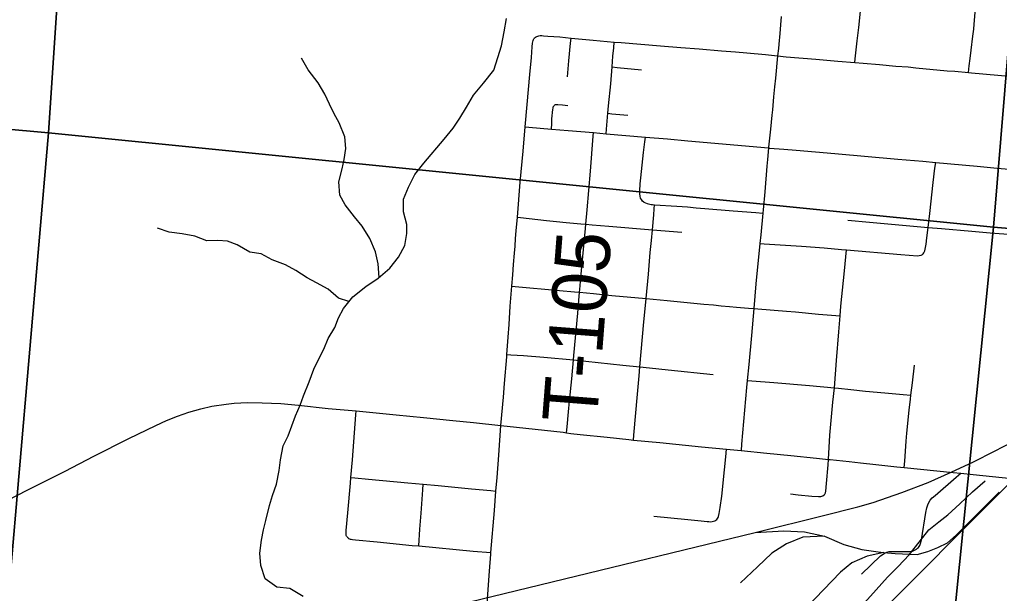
# Model space of a CAD drawing. Extents: x 0 to 1067, y 0 to 440.
# Drawn here: x 800.649 to 801.667, y 352.129 to 352.726 of the extents above; entities that cross this region are included whole.
import ezdxf

# ---------------------------------------------------------------- set-up
doc = ezdxf.new("R2010")
doc.units = 0
for name, color, linetype in [('GM_X_City_Street', 7, 'Continuous'), ('GM_X_County_Road', 7, 'Continuous'), ('GM_X_Minor_River', 7, 'Continuous'), ('GM_X_Rail_Line', 7, 'Continuous'), ('GM_X_Section', 7, 'Continuous'), ('GM_X_State_Route', 7, 'Continuous'), ('GM_X_Township_Road', 7, 'Continuous'), ('GM_X_Township_Road_Text', 7, 'Continuous'), ('GM_X_US_Route', 7, 'Continuous')]:
    doc.layers.add(name, color=color, linetype=linetype)

msp = doc.modelspace()

# ---------------------------------------------------------------- linework, layer by layer
at = {"layer": 'GM_X_City_Street'}
for p, q in [((801.2456, 352.6084), (801.2588, 352.6073)), ((801.2588, 352.6073), (801.2997, 352.6038))]:
    msp.add_line(p, q, dxfattribs=at)
for points in [[(801.5172, 352.6814), (801.5176, 352.685), (801.5184, 352.6915), (801.5198, 352.7039), (801.5214, 352.7179), (801.5236, 352.7383), (801.5243, 352.7457), (801.5246, 352.7506), (801.5256, 352.7626), (801.5278, 352.7882), (801.5297, 352.8098), (801.5302, 352.8166), (801.5309, 352.8233), (801.532, 352.8332), (801.5329, 352.8412), (801.5341, 352.8529), (801.5353, 352.8661), (801.5368, 352.883), (801.5376, 352.8918), (801.5379, 352.8957)], [(801.6353, 352.6709), (801.636, 352.6779), (801.6369, 352.6856), (801.638, 352.694), (801.6398, 352.7086), (801.6407, 352.7159), (801.6412, 352.7213), (801.6424, 352.7335), (801.6426, 352.7371), (801.6434, 352.7479), (801.6438, 352.7522)], [(801.186, 352.7081), (801.1869, 352.7085), (801.1879, 352.7089), (801.189, 352.7091), (801.1902, 352.7093), (801.191, 352.7093), (801.1918, 352.7093), (801.1936, 352.7092), (801.1981, 352.7089), (801.2107, 352.7079), (801.2223, 352.7066), (801.2453, 352.7045), (801.2672, 352.7026), (801.2744, 352.702), (801.3153, 352.6987), (801.3364, 352.697), (801.3556, 352.6955), (801.3785, 352.6935), (801.3933, 352.6925), (801.4051, 352.6915), (801.4243, 352.6896), (801.437, 352.6883), (801.4459, 352.6874), (801.4768, 352.6848), (801.4997, 352.6829), (801.5172, 352.6814), (801.5257, 352.6806), (801.543, 352.6792), (801.5597, 352.6777), (801.5727, 352.6767), (801.5807, 352.6759), (801.6131, 352.6728), (801.6211, 352.6722), (801.6353, 352.6709), (801.6385, 352.6706), (801.7086, 352.6645)], [(801.2186, 352.6663), (801.2201, 352.6832), (801.2218, 352.7016), (801.2223, 352.7066)], [(801.2588, 352.6073), (801.2592, 352.6119), (801.2602, 352.6246), (801.2605, 352.6285), (801.2611, 352.6363), (801.2636, 352.6591), (801.2651, 352.6767), (801.2659, 352.6881), (801.2667, 352.6965), (801.2672, 352.7026)], [(801.2651, 352.6767), (801.2702, 352.6762), (801.2956, 352.6737)], [(801.202, 352.6121), (801.2023, 352.6178), (801.2025, 352.6228), (801.2034, 352.6326), (801.2036, 352.634), (801.2039, 352.6352), (801.2043, 352.6361), (801.2049, 352.6367), (801.2056, 352.6372), (801.2063, 352.6375), (801.2071, 352.6376), (801.2086, 352.6376), (801.2136, 352.6372), (801.2188, 352.6368)], [(801.2605, 352.6285), (801.2648, 352.6281), (801.2814, 352.6267)], [(801.1747, 352.6144), (801.1785, 352.6141), (801.202, 352.6121)], [(801.202, 352.6121), (801.2193, 352.6107), (801.2456, 352.6084)], [(801.2176, 352.2963), (801.2182, 352.3023), (801.2198, 352.3179), (801.2208, 352.329), (801.2232, 352.3525), (801.2249, 352.3723), (801.2253, 352.3766), (801.2292, 352.4207), (801.2312, 352.4425), (801.2314, 352.4452), (801.2325, 352.4576), (801.2372, 352.5088), (801.2376, 352.5131), (801.2391, 352.528), (801.2425, 352.5684), (801.2453, 352.6046), (801.2456, 352.6084)], [(801.298, 352.5362), (801.2966, 352.5373), (801.2954, 352.5388), (801.2946, 352.5404), (801.2941, 352.5425), (801.2939, 352.5447), (801.2939, 352.5496), (801.294, 352.5533), (801.2942, 352.5552), (801.295, 352.5615), (801.2976, 352.5879), (801.2991, 352.599), (801.2997, 352.6038)], [(801.2997, 352.6038), (801.3227, 352.6018), (801.3437, 352.5998), (801.4275, 352.5925)], [(801.4275, 352.5925), (801.4284, 352.5924), (801.4433, 352.5911), (801.4563, 352.5901), (801.4965, 352.5867), (801.562, 352.5807), (801.588, 352.5786), (801.6012, 352.5774)], [(801.5861, 352.4809), (801.5874, 352.4817), (801.5882, 352.4825), (801.589, 352.4835), (801.5898, 352.4854), (801.5907, 352.4889), (801.5912, 352.4924), (801.592, 352.4989), (801.5933, 352.5098), (801.5951, 352.5244), (801.5986, 352.5566), (801.6005, 352.5714), (801.6012, 352.5774)], [(801.6012, 352.5774), (801.6442, 352.5736), (801.6652, 352.5716), (801.698, 352.5688)], [(801.298, 352.5362), (801.2996, 352.5354), (801.3013, 352.5348), (801.3027, 352.5344), (801.3042, 352.534), (801.3056, 352.5337), (801.3071, 352.5336), (801.309, 352.5334), (801.3321, 352.5319), (801.3433, 352.5311), (801.3525, 352.5302), (801.3612, 352.5296), (801.3908, 352.5271), (801.4142, 352.5252), (801.4216, 352.5246)], [(801.2871, 352.2887), (801.2876, 352.2939), (801.2914, 352.3366), (801.2931, 352.3556), (801.2939, 352.3647), (801.2981, 352.4116), (801.3001, 352.432), (801.3004, 352.4358), (801.3027, 352.4611), (801.3047, 352.4839), (801.3058, 352.4962), (801.3068, 352.5072), (801.3082, 352.5228), (801.3086, 352.5292), (801.309, 352.5334)], [(801.1665, 352.5206), (801.1698, 352.5202), (801.1968, 352.5171), (801.2071, 352.516), (801.2173, 352.515), (801.2325, 352.5136), (801.2376, 352.5131), (801.2442, 352.5127), (801.2615, 352.5113), (801.3068, 352.5072), (801.3375, 352.505)], [(801.5101, 352.5173), (801.5324, 352.5153), (801.5933, 352.5098), (801.6074, 352.5086), (801.6387, 352.5058), (801.658, 352.5042), (801.6864, 352.5022), (801.7286, 352.4997), (801.7295, 352.4996), (801.7413, 352.4985), (801.753, 352.4974), (801.7634, 352.4961), (801.7689, 352.4953)], [(801.4186, 352.4932), (801.423, 352.4929), (801.4619, 352.4903), (801.4854, 352.4885), (801.5033, 352.487), (801.5086, 352.4864), (801.565, 352.4817), (801.5824, 352.4804), (801.5842, 352.4805), (801.5861, 352.4809)], [(801.4898, 352.2686), (801.4913, 352.2939), (801.4943, 352.328), (801.496, 352.343), (801.498, 352.3713), (801.5005, 352.4011), (801.5019, 352.4179), (801.5028, 352.4281), (801.5055, 352.4546), (801.5066, 352.4648), (801.5086, 352.4864)], [(801.1609, 352.4487), (801.1641, 352.4484), (801.2103, 352.4442), (801.2258, 352.443), (801.2312, 352.4425), (801.2456, 352.4411), (801.2647, 352.4392), (801.3004, 352.4358), (801.3222, 352.434), (801.3604, 352.4302), (801.3703, 352.4292), (801.3783, 352.4284), (801.3869, 352.4276), (801.3943, 352.4269), (801.4066, 352.4259), (801.4121, 352.4254), (801.4333, 352.4238), (801.4463, 352.4228), (801.4555, 352.422), (801.4794, 352.4198), (801.4976, 352.4183), (801.5019, 352.4179)], [(801.1557, 352.3778), (801.1599, 352.3775), (801.1729, 352.3767), (801.1942, 352.375), (801.2249, 352.3723), (801.2761, 352.3665), (801.2939, 352.3647), (801.3039, 352.3637), (801.3231, 352.3617), (801.3699, 352.3569)], [(801.5685, 352.26), (801.569, 352.2666), (801.5707, 352.2875), (801.5714, 352.2959), (801.5736, 352.3199), (801.5749, 352.3311), (801.5754, 352.3353), (801.5771, 352.3483), (801.5791, 352.3666)], [(801.4054, 352.3506), (801.4101, 352.3503), (801.4331, 352.3487), (801.4701, 352.3455), (801.496, 352.343), (801.5002, 352.3426), (801.5132, 352.3414), (801.5282, 352.3397), (801.5484, 352.3379), (801.5675, 352.336), (801.5754, 352.3353)], [(801.3729, 352.2055), (801.3737, 352.2062), (801.3746, 352.2073), (801.3751, 352.2082), (801.3755, 352.2093), (801.3762, 352.2123), (801.3773, 352.2185), (801.3789, 352.2302), (801.3817, 352.2579), (801.383, 352.2714), (801.3838, 352.2794)], [(801.4504, 352.2329), (801.4584, 352.2319), (801.4726, 352.2305), (801.4794, 352.2299), (801.4806, 352.2299), (801.4819, 352.2301), (801.483, 352.2303), (801.484, 352.2308), (801.4852, 352.2317), (801.486, 352.2326), (801.4866, 352.2337), (801.487, 352.2354), (801.4879, 352.2435), (801.4894, 352.2631), (801.4898, 352.2686)], [(801.5866, 352.1848), (801.591, 352.2133), (801.592, 352.2181), (801.5929, 352.2212), (801.5941, 352.2239), (801.5956, 352.2263), (801.5976, 352.2285), (801.6006, 352.231), (801.6226, 352.25), (801.6275, 352.2542)], [(801.3085, 352.2095), (801.3435, 352.2062), (801.3576, 352.2046), (801.3639, 352.204), (801.3655, 352.2039), (801.3674, 352.2038), (801.3688, 352.2039), (801.3703, 352.2042), (801.3717, 352.2048), (801.3729, 352.2055)], [(801.5241, 352.1494), (801.544, 352.1684), (801.5477, 352.1707), (801.5505, 352.172), (801.5529, 352.1727), (801.5553, 352.1729), (801.5726, 352.1728), (801.5742, 352.1729), (801.576, 352.1731), (801.5771, 352.1733), (801.5785, 352.1737), (801.5799, 352.1744), (801.5813, 352.1754), (801.5823, 352.1762), (801.5832, 352.1771), (801.5839, 352.1781), (801.5846, 352.1791), (801.5855, 352.1813), (801.5866, 352.1848)]]:
    msp.add_lwpolyline(points, dxfattribs=at)
at = {"layer": 'GM_X_County_Road'}
for p, q in [((801.1472, 352.2729), (801.1495, 352.3038)), ((801.1454, 352.2498), (801.1472, 352.2729)), ((801.1442, 352.2357), (801.1454, 352.2498))]:
    msp.add_line(p, q, dxfattribs=at)
for points in [[(801.1391, 352.1719), (801.1426, 352.2153), (801.1442, 352.2357)], [(801.1317, 352.0792), (801.1337, 352.0999), (801.1348, 352.1135), (801.1359, 352.1284), (801.1376, 352.1523), (801.139, 352.1702), (801.1391, 352.1719)]]:
    msp.add_lwpolyline(points, dxfattribs=at)
at = {"layer": 'GM_X_Minor_River'}
for points in [[(800.9441, 352.1259), (800.9302, 352.1345), (800.9165, 352.1358), (800.9045, 352.1444), (800.8999, 352.1581), (800.8989, 352.1711), (800.9007, 352.1847), (800.9028, 352.1953), (800.9052, 352.2051), (800.9089, 352.2206), (800.9121, 352.2312), (800.9162, 352.2429), (800.9191, 352.2569), (800.9204, 352.2683), (800.9233, 352.2827), (800.9284, 352.2932), (800.932, 352.3034), (800.936, 352.314), (800.9407, 352.3249), (800.9443, 352.3347), (800.9503, 352.3491), (800.9551, 352.3626), (800.9598, 352.3724), (800.9653, 352.3834), (800.9701, 352.3943), (800.9767, 352.4056), (800.9807, 352.4158), (800.9858, 352.4255), (800.9955, 352.4375), (801.009, 352.4483), (801.022, 352.4572), (801.034, 352.4673), (801.0429, 352.4789), (801.0496, 352.4909), (801.0517, 352.5034), (801.0515, 352.5129), (801.0483, 352.5259), (801.0481, 352.5392), (801.0533, 352.5516), (801.06, 352.5648), (801.0693, 352.5768), (801.0906, 352.6015), (801.0999, 352.6131), (801.1066, 352.6236), (801.1136, 352.6349), (801.121, 352.6473), (801.1315, 352.66), (801.142, 352.6735), (801.1464, 352.6864), (801.15, 352.6988), (801.1529, 352.7132), (801.1551, 352.7272)], [(801.0228, 352.4579), (801.0219, 352.472), (801.0191, 352.4846), (801.0133, 352.4984), (801.0051, 352.511), (800.9973, 352.5207), (800.9877, 352.5334), (800.9822, 352.5433), (800.9809, 352.5574), (800.9845, 352.5706), (800.9866, 352.5805), (800.9883, 352.5918), (800.9874, 352.604), (800.9812, 352.6185), (800.9761, 352.6281), (800.9713, 352.6381), (800.9666, 352.6484), (800.9596, 352.6603), (800.9492, 352.6738), (800.9422, 352.686)], [(800.9915, 352.4327), (800.9807, 352.4363), (800.9698, 352.4456), (800.9578, 352.4522), (800.948, 352.4573), (800.9364, 352.4651), (800.9255, 352.471), (800.9119, 352.4762), (800.9002, 352.4824), (800.8885, 352.4842), (800.8754, 352.4916), (800.8652, 352.4956), (800.8553, 352.4961), (800.8439, 352.4959), (800.8315, 352.5007), (800.8182, 352.5032), (800.8046, 352.5049), (800.7925, 352.5089)], [(801.5274, 352.1194), (801.5394, 352.1329), (801.551, 352.146), (801.5622, 352.1572), (801.5738, 352.1695), (801.5839, 352.1826), (801.594, 352.1954), (801.6044, 352.2035), (801.614, 352.211), (801.6263, 352.2225), (801.6395, 352.2348), (801.6526, 352.2464)]]:
    msp.add_lwpolyline(points, dxfattribs=at)
at = {"layer": 'GM_X_Rail_Line'}
for points in [[(801.7963, 352.3629), (801.5416, 352.1069), (801.3639, 351.9272)], [(801.4135, 352.1927), (801.4165, 352.1934), (801.4833, 352.2098), (801.5202, 352.2193), (801.5362, 352.2239), (801.5662, 352.2341), (801.5935, 352.2446), (801.6174, 352.2552), (801.6406, 352.2659), (801.6625, 352.2772), (801.681, 352.287)], [(801.5473, 352.1718), (801.5592, 352.1707), (801.5819, 352.1697), (801.5931, 352.1727), (801.6036, 352.177), (801.6135, 352.1819), (801.6224, 352.1898), (801.6671, 352.2345)], [(800.6415, 352.0032), (800.9919, 352.0898), (801.4135, 352.1927)], [(801.4856, 352.1888), (801.4632, 352.1878), (801.4461, 352.1809), (801.431, 352.171), (801.4162, 352.1569), (801.3984, 352.1401)], [(801.4135, 352.1927), (801.4435, 352.1944), (801.4649, 352.1934), (801.4856, 352.1888)], [(801.4856, 352.1888), (801.5056, 352.1802), (801.5244, 352.175), (801.5415, 352.1724), (801.5473, 352.1718)], [(801.5473, 352.1718), (801.53, 352.1681), (801.5142, 352.1612), (801.5023, 352.1513), (801.4586, 352.1059), (801.4093, 352.054)]]:
    msp.add_lwpolyline(points, dxfattribs=at)
at = {"layer": 'GM_X_Section'}
for points in [[(799.6925, 353.7106), (800.7452, 353.5961), (800.6794, 352.6083), (799.6121, 352.7044)], [(800.7452, 353.5961), (801.7432, 353.4993), (801.6612, 352.5101), (800.6794, 352.6083)], [(801.7432, 353.4993), (802.7829, 353.4125), (802.6931, 352.4236), (801.6612, 352.5101)], [(799.6121, 352.7044), (800.6794, 352.6083), (800.6286, 352.0258), (800.5587, 351.5925), (799.5337, 351.7084)], [(800.6794, 352.6083), (801.6612, 352.5101), (801.5595, 351.4988), (800.5587, 351.5925), (800.6286, 352.0258)], [(802.6931, 352.4236), (802.5998, 351.3996), (801.5595, 351.4988), (801.6612, 352.5101)]]:
    msp.add_lwpolyline(points, close=True, dxfattribs=at)
at = {"layer": 'GM_X_State_Route'}
for p, q in [((801.5685, 352.26), (801.6195, 352.2551)), ((801.6195, 352.2551), (801.6275, 352.2542))]:
    msp.add_line(p, q, dxfattribs=at)
for points in [[(801.4406, 352.7291), (801.4388, 352.7075), (801.4386, 352.7045), (801.4378, 352.6959), (801.437, 352.6883), (801.4347, 352.6651), (801.4337, 352.6559), (801.4328, 352.6456), (801.4315, 352.632), (801.4309, 352.6266), (801.4295, 352.612), (801.4276, 352.5933), (801.4275, 352.5925), (801.4263, 352.5803), (801.4258, 352.5735), (801.4236, 352.5468), (801.422, 352.5283), (801.4216, 352.5246), (801.4195, 352.5023), (801.4186, 352.4932), (801.4143, 352.4513), (801.4121, 352.4254), (801.4097, 352.3973), (801.407, 352.3673), (801.4054, 352.3506), (801.4048, 352.3435), (801.3996, 352.2844), (801.3991, 352.278)], [(801.3991, 352.278), (801.4257, 352.2751), (801.4508, 352.2725), (801.4773, 352.2699), (801.4898, 352.2686)], [(801.4898, 352.2686), (801.4916, 352.2685), (801.5114, 352.2664), (801.5231, 352.265), (801.5391, 352.2632), (801.5607, 352.2607), (801.5685, 352.26)], [(801.6275, 352.2542), (801.64, 352.2529), (801.6805, 352.2487)]]:
    msp.add_lwpolyline(points, dxfattribs=at)
at = {"layer": 'GM_X_Township_Road'}
for points in [[(801.1747, 352.6144), (801.1768, 352.6378), (801.1794, 352.6687), (801.1811, 352.6866), (801.182, 352.6975), (801.1823, 352.7014), (801.1826, 352.7028), (801.183, 352.7041), (801.1834, 352.7052), (801.1837, 352.7058), (801.1841, 352.7064), (801.1845, 352.7069), (801.1854, 352.7077), (801.186, 352.7081)], [(801.1665, 352.5206), (801.1696, 352.5569), (801.1716, 352.5785), (801.1725, 352.589), (801.1747, 352.6144)], [(801.1609, 352.4487), (801.1619, 352.4606), (801.1626, 352.4713), (801.1634, 352.4829), (801.1641, 352.4903), (801.1647, 352.4983), (801.1653, 352.5064), (801.1665, 352.5206)], [(801.1557, 352.3778), (801.157, 352.3958), (801.1579, 352.4088), (801.1592, 352.428), (801.1609, 352.4487)], [(801.1495, 352.3038), (801.152, 352.3333), (801.1533, 352.3475), (801.1555, 352.3754), (801.1557, 352.3778)], [(800.9936, 352.2497), (800.9951, 352.268), (800.9986, 352.3148), (800.9989, 352.319)], [(800.9895, 352.1879), (800.9891, 352.1886), (800.9888, 352.1894), (800.9886, 352.1902), (800.9885, 352.191), (800.9885, 352.1918), (800.9886, 352.1927), (800.9887, 352.1948), (800.9903, 352.2131), (800.9932, 352.244), (800.9936, 352.2497)], [(800.9936, 352.2497), (800.9977, 352.2493), (801.0119, 352.2481), (801.0526, 352.2443), (801.0686, 352.2428)], [(801.064, 352.1786), (801.0652, 352.1961), (801.0665, 352.2128), (801.0682, 352.2368), (801.0686, 352.2428)], [(801.0686, 352.2428), (801.0843, 352.2413), (801.1189, 352.2381), (801.139, 352.2362), (801.1442, 352.2357)], [(800.9895, 352.1879), (800.99, 352.1874), (800.9906, 352.1869), (800.9912, 352.1865), (800.9921, 352.1861), (800.9929, 352.1858), (800.9939, 352.1856), (800.9953, 352.1853), (800.9983, 352.1849), (801.0207, 352.183), (801.0573, 352.1792), (801.064, 352.1786)], [(801.064, 352.1786), (801.1207, 352.1733), (801.1391, 352.1719)]]:
    msp.add_lwpolyline(points, dxfattribs=at)
at = {"layer": 'GM_X_US_Route'}
for p, q in [((801.5685, 352.26), (801.6195, 352.2551)), ((801.6195, 352.2551), (801.6275, 352.2542))]:
    msp.add_line(p, q, dxfattribs=at)
for points in [[(800.6167, 352.2158), (800.6571, 352.2366), (800.6965, 352.2564), (800.7263, 352.2718), (800.7629, 352.2904), (800.7907, 352.304), (800.802, 352.3091), (800.8135, 352.3137), (800.8252, 352.3177), (800.8377, 352.3212), (800.8492, 352.3238), (800.8638, 352.3262), (800.8724, 352.327), (800.886, 352.3276), (800.9015, 352.3275), (800.9207, 352.3266), (800.9392, 352.325), (800.9701, 352.3217), (800.9989, 352.319), (801.0406, 352.315), (801.069, 352.3121), (801.0993, 352.3092), (801.1209, 352.3068), (801.1495, 352.3038)], [(801.1495, 352.3038), (801.1658, 352.302), (801.2141, 352.2968), (801.2176, 352.2963), (801.2221, 352.2957), (801.2319, 352.2945), (801.2597, 352.2916), (801.2825, 352.2892), (801.2871, 352.2887), (801.3146, 352.286), (801.3578, 352.2817), (801.3838, 352.2794), (801.3914, 352.2787), (801.3991, 352.278)], [(801.3991, 352.278), (801.4257, 352.2751), (801.4508, 352.2725), (801.4773, 352.2699), (801.4898, 352.2686)], [(801.4898, 352.2686), (801.4916, 352.2685), (801.5114, 352.2664), (801.5231, 352.265), (801.5391, 352.2632), (801.5607, 352.2607), (801.5685, 352.26)], [(801.6275, 352.2542), (801.64, 352.2529), (801.6805, 352.2487)]]:
    msp.add_lwpolyline(points, dxfattribs=at)

# ---------------------------------------------------------------- texts
at = {"layer": 'GM_X_Township_Road_Text'}
msp.add_text('T-105', height=0.05682, rotation=85.5147, dxfattribs=at).set_placement((801.2489, 352.3054))

doc.saveas('drawing.dxf')
